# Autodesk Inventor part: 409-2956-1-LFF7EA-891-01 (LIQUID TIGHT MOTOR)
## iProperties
Created: 2011-01
Part Number: 409-2956-1-LFF7EA-891-01 (LIQUID TIGHT MOTOR)
Material: 1" LIQUID TIGHT
Document SubType Name: Modeling
Designer: S. Boerckel
Engineer: Steve Boerckel
Mass: 358.747 g
Surface Area: 1136.16 cm^2
Volume: 256.248 cm^3
Density: 1.4 g/cm^3
Author: S. Boerckel
Revision Number: 0
LGTH: 22.534 in
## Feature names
1. Sweep1
